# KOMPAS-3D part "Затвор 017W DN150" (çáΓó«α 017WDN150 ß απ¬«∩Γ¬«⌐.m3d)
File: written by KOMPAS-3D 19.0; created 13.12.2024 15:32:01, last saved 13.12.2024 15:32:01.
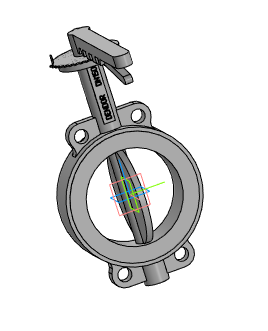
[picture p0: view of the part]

Document properties: Автор: Евгений; Полное имя файла: ..\Затвор 017WDN150.a3d

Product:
- Part/product: Затвор 017W DN150
    Масса: 20.3775

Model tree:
1. Операция без истории:1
